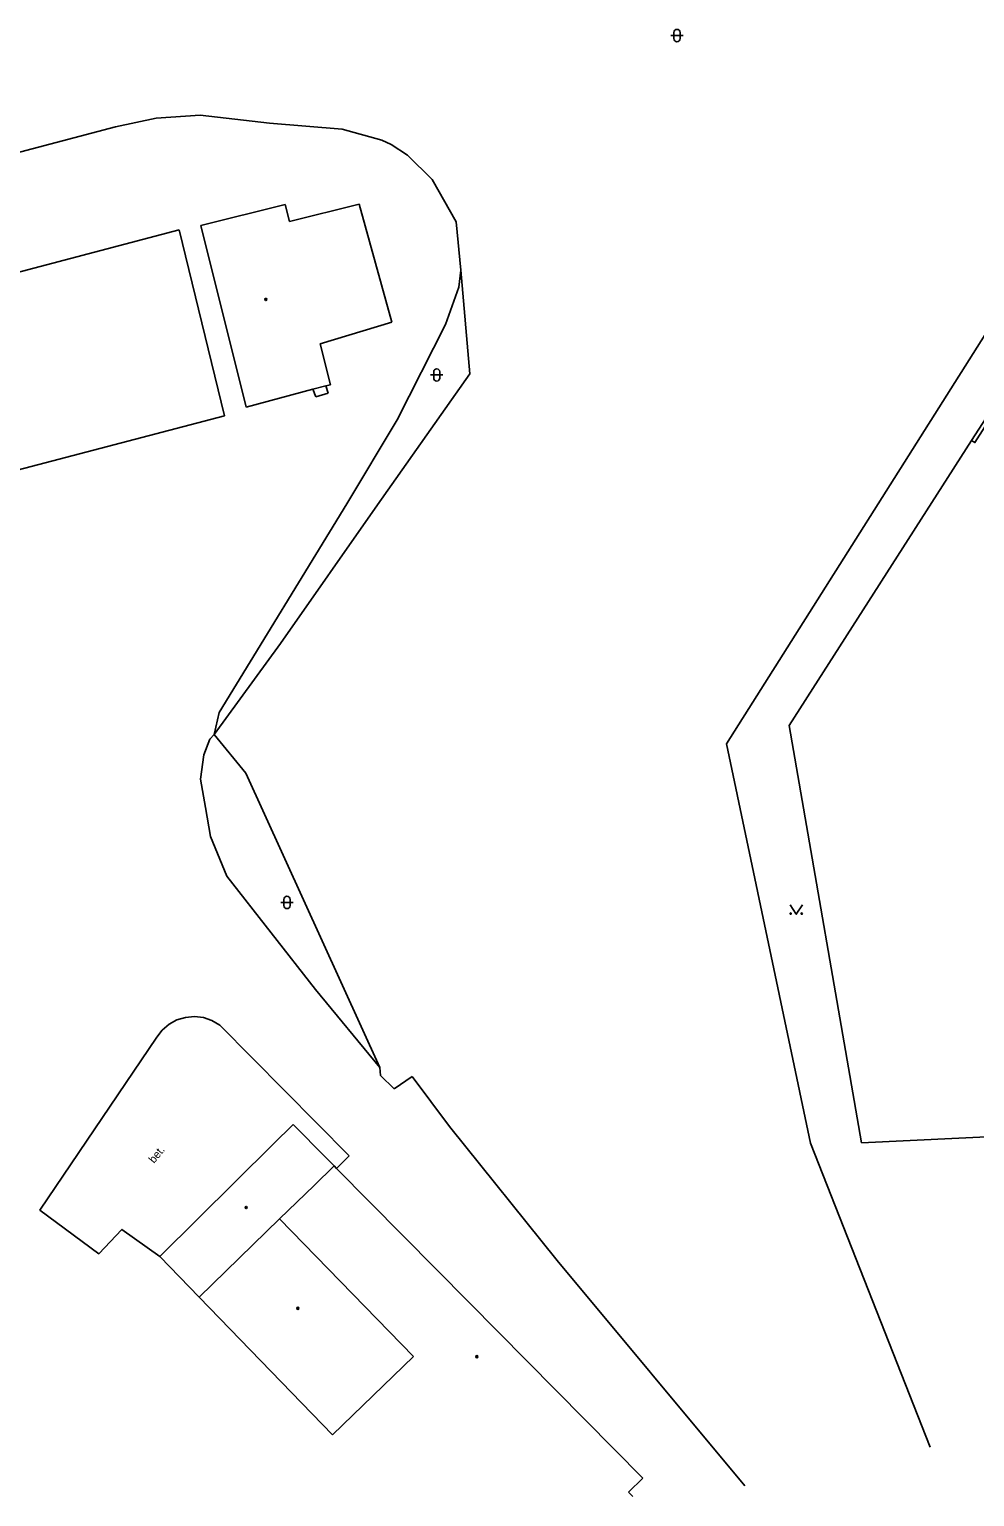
# Model space of a CAD drawing. Extents: x -598341 to -594502, y -1162301 to -1161406.
# Drawn here: x -594911.9 to -594835.2, y -1161757 to -1161637.9 of the extents above; entities that cross this region are included whole.
import ezdxf

# ---------------------------------------------------------------- set-up
doc = ezdxf.new("R2010")
doc.units = 0
for name, color, linetype in [('Vrstva 10', 7, 'Continuous'), ('Vrstva 11', 7, 'Continuous'), ('Vrstva 36', 7, 'Continuous'), ('Vrstva 39', 7, 'Continuous'), ('Vrstva 40', 7, 'Continuous'), ('Vrstva 5', 7, 'Continuous'), ('Vrstva 7', 7, 'Continuous')]:
    doc.layers.add(name, color=color, linetype=linetype)

msp = doc.modelspace()

# ---------------------------------------------------------------- linework, layer by layer
at = {"layer": 'Vrstva 10'}
for p in [(-594896.47, -1161718.72), (-594887, -1161730.35)]:
    msp.add_line(p, (-594885.97, -1161729.33), dxfattribs=at)
for points in [[(-594896.47, -1161718.72), (-594897.1, -1161718.35), (-594897.79, -1161718.11), (-594898.52, -1161718.02), (-594899.24, -1161718.09), (-594899.94, -1161718.3), (-594900.58, -1161718.65), (-594901.14, -1161719.13), (-594901.58, -1161719.71)], [(-594901.33, -1161737.52), (-594904.41, -1161735.31), (-594906.27, -1161737.29), (-594911.07, -1161733.74), (-594901.58, -1161719.71)]]:
    msp.add_lwpolyline(points, dxfattribs=at)
at = {"layer": 'Vrstva 11'}
for p, q in [((-594898.06, -1161644.82), (-594901.64, -1161645.08)), ((-594892.44, -1161645.48), (-594898.06, -1161644.82)), ((-594904.92, -1161645.77), (-594923.75, -1161650.72)), ((-594901.64, -1161645.08), (-594904.92, -1161645.77)), ((-594886.53, -1161645.96), (-594892.44, -1161645.48)), ((-594883.32, -1161646.86), (-594886.53, -1161645.96)), ((-594823.75, -1161645.82), (-594855.34, -1161695.88)), ((-594882.55, -1161647.22), (-594883.32, -1161646.86)), ((-594881.23, -1161648.08), (-594882.55, -1161647.22)), ((-594879.22, -1161650.05), (-594881.23, -1161648.08)), ((-594877.27, -1161653.48), (-594879.22, -1161650.05)), ((-594876.91, -1161657.4), (-594877.27, -1161653.48)), ((-594877.05, -1161658.8), (-594876.91, -1161657.4)), ((-594876.16, -1161665.82), (-594876.91, -1161657.4)), ((-594878.14, -1161661.83), (-594877.05, -1161658.8)), ((-594882.06, -1161669.57), (-594878.14, -1161661.83)), ((-594883.65, -1161676.48), (-594876.16, -1161665.82)), ((-594888.68, -1161667.71), (-594888.91, -1161667.08)), ((-594887.68, -1161667.4), (-594888.68, -1161667.71)), ((-594887.85, -1161666.81), (-594887.68, -1161667.4)), ((-594886.16, -1161676.39), (-594882.06, -1161669.57)), ((-594896.52, -1161693.32), (-594886.16, -1161676.39)), ((-594891.53, -1161687.73), (-594883.65, -1161676.48)), ((-594896.93, -1161695.12), (-594891.53, -1161687.73)), ((-594896.93, -1161695.12), (-594896.52, -1161693.32)), ((-594897.77, -1161696.78), (-594897.27, -1161695.51)), ((-594897.27, -1161695.51), (-594896.93, -1161695.12)), ((-594894.36, -1161698.26), (-594896.93, -1161695.12)), ((-594855.34, -1161695.88), (-594848.53, -1161728.3)), ((-594898.02, -1161698.74), (-594897.77, -1161696.78)), ((-594883.48, -1161722.17), (-594894.36, -1161698.26)), ((-594897.62, -1161701.06), (-594898.02, -1161698.74)), ((-594897.22, -1161703.41), (-594897.62, -1161701.06)), ((-594895.89, -1161706.61), (-594897.22, -1161703.41)), ((-594888.7, -1161715.82), (-594895.89, -1161706.61)), ((-594883.48, -1161722.17), (-594888.7, -1161715.82)), ((-594883.42, -1161722.8), (-594883.48, -1161722.17)), ((-594882.32, -1161723.9), (-594883.42, -1161722.8)), ((-594880.86, -1161722.89), (-594882.32, -1161723.9)), ((-594877.83, -1161726.94), (-594880.86, -1161722.89)), ((-594869.08, -1161737.82), (-594877.83, -1161726.94)), ((-594848.53, -1161728.3), (-594838.8, -1161752.98)), ((-594844.39, -1161728.29), (-594830.92, -1161727.62)), ((-594853.85, -1161756.13), (-594869.08, -1161737.82))]:
    msp.add_line(p, q, dxfattribs=at)
at = {"layer": 'Vrstva 36'}
for p, q in [((-594859.86, -1161638.36), (-594858.86, -1161638.36)), ((-594859.61, -1161638.11), (-594859.61, -1161638.61)), ((-594859.11, -1161638.11), (-594859.11, -1161638.61)), ((-594879.35, -1161665.92), (-594878.35, -1161665.92)), ((-594879.1, -1161665.67), (-594879.1, -1161666.17)), ((-594878.6, -1161665.67), (-594878.6, -1161666.17)), ((-594891.51, -1161708.76), (-594890.51, -1161708.76)), ((-594891.26, -1161708.51), (-594891.26, -1161709.01)), ((-594890.76, -1161708.51), (-594890.76, -1161709.01))]:
    msp.add_line(p, q, dxfattribs=at)
msp.add_lwpolyline([(-594850.18, -1161708.96), (-594849.68, -1161709.71), (-594849.18, -1161708.96)], dxfattribs=at)
for centre in [(-594850.13, -1161709.66), (-594849.23, -1161709.66)]:
    msp.add_circle(centre, 0.05, dxfattribs=at)
for centre, start, end in [((-594859.36, -1161638.11), 0, 180), ((-594859.36, -1161638.61), 180, 0), ((-594878.85, -1161665.67), 0, 180), ((-594878.85, -1161666.17), 180, 0), ((-594891.01, -1161708.51), 0, 180), ((-594891.01, -1161709.01), 180, 0)]:
    msp.add_arc(centre, 0.25, start, end, dxfattribs=at)
at = {"layer": 'Vrstva 39'}
for centre, radius in [((-594892.73, -1161659.79), 0.09), ((-594892.73, -1161659.79), 0.0398), ((-594894.32, -1161733.53), 0.09), ((-594894.32, -1161733.53), 0.0398), ((-594890.13, -1161741.71), 0.09), ((-594890.13, -1161741.71), 0.0398), ((-594875.6, -1161745.65), 0.09), ((-594875.6, -1161745.65), 0.0398)]:
    msp.add_circle(centre, radius, dxfattribs=at)
at = {"layer": 'Vrstva 5'}
for p, q in [((-594890.8, -1161653.46), (-594885.16, -1161652.05)), ((-594885.16, -1161652.05), (-594882.49, -1161661.64)), ((-594898.01, -1161653.79), (-594891.15, -1161652.07)), ((-594891.15, -1161652.07), (-594890.8, -1161653.46)), ((-594912.98, -1161657.62), (-594899.76, -1161654.15)), ((-594899.76, -1161654.15), (-594896.08, -1161669.25)), ((-594894.31, -1161668.55), (-594898.01, -1161653.79)), ((-594882.49, -1161661.64), (-594888.31, -1161663.39)), ((-594888.31, -1161663.39), (-594887.48, -1161666.72)), ((-594888.91, -1161667.08), (-594894.31, -1161668.55)), ((-594887.85, -1161666.81), (-594888.91, -1161667.08)), ((-594887.48, -1161666.72), (-594887.85, -1161666.81)), ((-594896.08, -1161669.25), (-594928.09, -1161677.64)), ((-594892.13, -1161728.39), (-594890.51, -1161726.79)), ((-594890.51, -1161726.79), (-594887.87, -1161729.46)), ((-594901.33, -1161737.52), (-594892.13, -1161728.39)), ((-594887.87, -1161729.46), (-594887.19, -1161730.15)), ((-594888.81, -1161731.74), (-594887.19, -1161730.15)), ((-594887.19, -1161730.15), (-594887, -1161730.35)), ((-594887, -1161730.35), (-594876.22, -1161741.24)), ((-594888.81, -1161731.74), (-594891.61, -1161734.46)), ((-594898.15, -1161740.81), (-594891.61, -1161734.46)), ((-594891.61, -1161734.46), (-594880.73, -1161745.63)), ((-594898.15, -1161740.81), (-594901.33, -1161737.52)), ((-594887.32, -1161751.99), (-594898.15, -1161740.81)), ((-594876.22, -1161741.24), (-594862.12, -1161755.5)), ((-594887.32, -1161751.99), (-594880.73, -1161745.63)), ((-594862.12, -1161755.5), (-594863.3, -1161756.65)), ((-594863.3, -1161756.65), (-594862.95, -1161757.01))]:
    msp.add_line(p, q, dxfattribs=at)
at = {"layer": 'Vrstva 7'}
msp.add_line((-594819.46, -1161646.3), (-594835.44, -1161671.25), dxfattribs=at)
for points in [[(-594835.44, -1161671.25), (-594835.18, -1161671.42), (-594819.37, -1161646.64), (-594799.77, -1161648.3)], [(-594844.39, -1161728.29), (-594850.24, -1161694.38), (-594835.44, -1161671.25)]]:
    msp.add_lwpolyline(points, dxfattribs=at)

# ---------------------------------------------------------------- texts
at = {"layer": 'Vrstva 40'}
msp.add_text('bet.', height=0.65, rotation=50.7228, dxfattribs=at).set_placement((-594901.8, -1161729.99))

doc.saveas('drawing.dxf')
